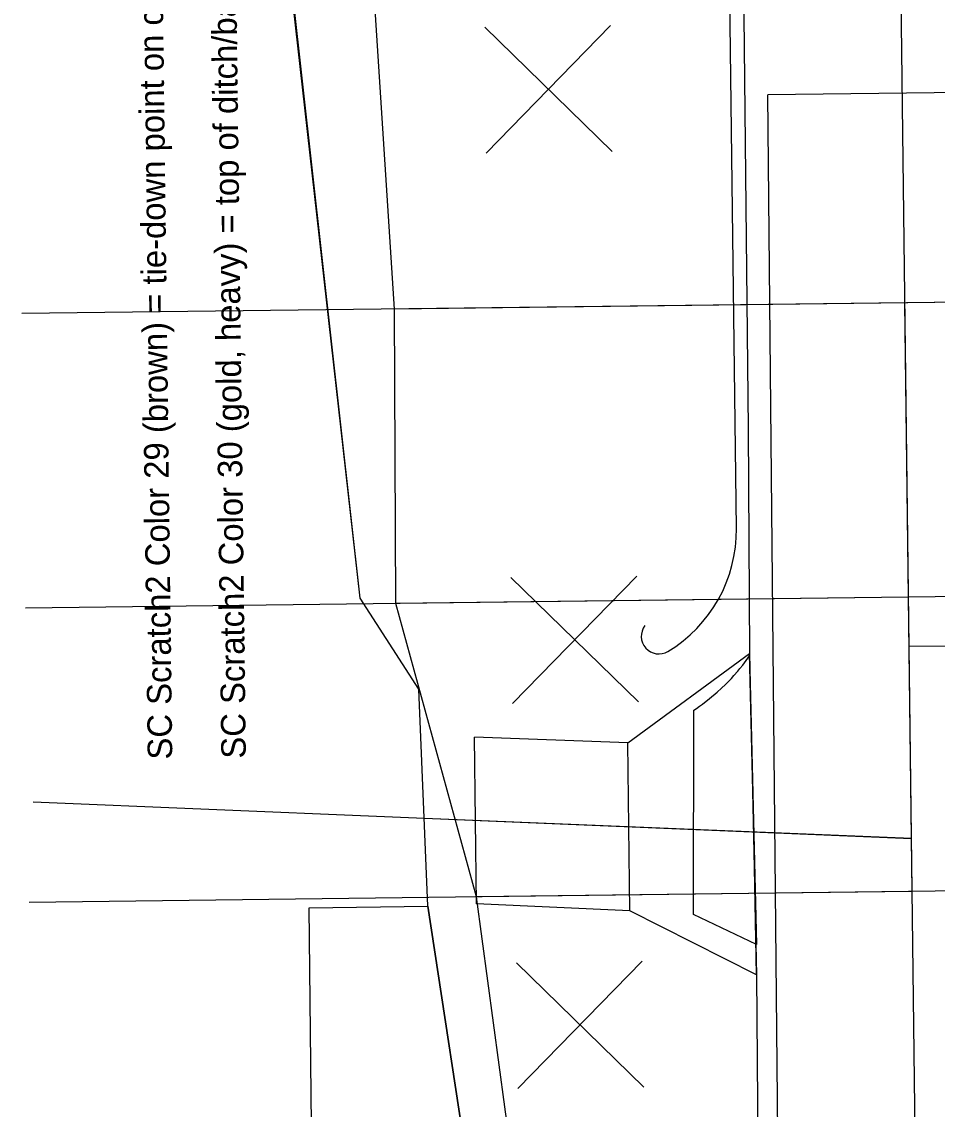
# Model space of a CAD drawing. Extents: x 2341000 to 2341204, y 624110 to 624511.
# Drawn here: x 2341052 to 2341129.8, y 624192 to 624284.3 of the extents above; entities that cross this region are included whole.
import ezdxf

# ---------------------------------------------------------------- set-up
doc = ezdxf.new("R2010")
doc.units = 0
for name, color, linetype in [('Default', 7, 'Continuous'), ('GE_P_Driveway_CL', 7, 'Continuous'), ('PV_P_Drive', 7, 'Continuous'), ('RD_P_GR_Lt', 7, 'Continuous'), ('RD_P_GR_Rt', 7, 'Continuous'), ('RW_P_Const_Limits', 7, 'Continuous'), ('SC_Scratch1', 7, 'Continuous'), ('SC_Scratch10', 7, 'Continuous'), ('SC_Scratch2', 7, 'Continuous'), ('SC_Scratch5', 7, 'Continuous'), ('VG_P_Cells', 7, 'Continuous')]:
    doc.layers.add(name, color=color, linetype=linetype)

msp = doc.modelspace()

# ---------------------------------------------------------------- linework, layer by layer
at = {"layer": 'Default'}
msp.add_line((2341127.658, 624210.478), (2341127.04, 624260.474), dxfattribs=at)
at = {"layer": 'GE_P_Driveway_CL'}
for p, q in [((2341165.46, 624231.741), (2341127.401, 624231.271)), ((2341127.602, 624214.968), (2341087.637, 624216.637))]:
    msp.add_line(p, q, dxfattribs=at)
at = {"layer": 'PV_P_Drive'}
for p, q in [((2341103.5, 624223.114), (2341113.849, 624230.689)), ((2341103.5, 624223.114), (2341090.493, 624223.587)), ((2341090.668, 624209.433), (2341090.493, 624223.587)), ((2341103.676, 624208.846), (2341103.5, 624223.114)), ((2341103.676, 624208.846), (2341090.668, 624209.433)), ((2341114.426, 624203.393), (2341103.676, 624208.846))]:
    msp.add_line(p, q, dxfattribs=at)
msp.add_lwpolyline([(2341114.426, 624203.393), (2341114.204, 624215.528), (2341113.849, 624230.689)], dxfattribs=at)
at = {"layer": 'RD_P_GR_Lt'}
msp.add_line((2341112.726, 624241.296), (2341111.351, 624353.788), dxfattribs=at)
msp.add_arc((2341106.147, 624232.157), 1.5, 143.11049, 300.54947, dxfattribs=at)
at = {"layer": 'RD_P_GR_Rt'}
msp.add_arc((2341100.726, 624241.149), 12, 301.01684, 0.69994, dxfattribs=at)
at = {"layer": 'RW_P_Const_Limits'}
for p, q in [((2341080.795, 624235.399), (2341074.081, 624295.577)), ((2341136.675, 624278.386), (2341115.404, 624278.123)), ((2341116.866, 624125.338), (2341115.404, 624278.123)), ((2341085.756, 624227.657), (2341080.795, 624235.399)), ((2341086.536, 624209.244), (2341085.756, 624227.657))]:
    msp.add_line(p, q, dxfattribs=at)
msp.add_lwpolyline([(2341099.96, 624125.129), (2341096.852, 624159.643), (2341090.335, 624184.21), (2341086.536, 624209.244)], dxfattribs=at)
at = {"layer": 'SC_Scratch1'}
for p, q in [((2341202.034, 624261.401), (2341052.046, 624259.548)), ((2341202.343, 624236.403), (2341052.355, 624234.55)), ((2341053.02, 624218.083), (2341127.602, 624214.968)), ((2341202.652, 624211.405), (2341052.663, 624209.551))]:
    msp.add_line(p, q, dxfattribs=at)
at = {"layer": 'SC_Scratch10'}
msp.add_lwpolyline([(2341113.217, 624298.306), (2341113.72, 624249.79), (2341113.849, 624230.689), (2341114.426, 624203.393), (2341114.82, 624152.66), (2341115.05, 624125.316), (2341099.96, 624125.129), (2341096.852, 624159.643), (2341090.335, 624184.21), (2341086.536, 624209.244), (2341085.756, 624227.657), (2341080.795, 624235.399), (2341072.845, 624305.648)], dxfattribs=at)
msp.add_lwpolyline([(2341099.96, 624125.129), (2341077.357, 624124.82), (2341076.437, 624209.095), (2341086.536, 624209.244), (2341090.335, 624184.21), (2341096.852, 624159.643)], close=True, dxfattribs=at)
at = {"layer": 'SC_Scratch2'}
for p, q in [((2341128.275, 624160.482), (2341124.26, 624485.457)), ((2341155.108, 624260.821), (2341083.683, 624259.939)), ((2341127.349, 624235.476), (2341083.802, 624234.938)), ((2341127.658, 624210.478), (2341090.661, 624210.021))]:
    msp.add_line(p, q, dxfattribs=at)
for points in [[(2341100.878, 624160.143), (2341094.029, 624185.061), (2341090.661, 624210.021), (2341083.802, 624234.938), (2341083.683, 624259.939), (2341082.074, 624284.921), (2341082.174, 624297.923), (2341086.008, 624308.971), (2341075.627, 624317.843), (2341092.175, 624327.049), (2341094.859, 624338.083), (2341094.767, 624360.083), (2341092.498, 624385.057), (2341096.909, 624410.113), (2341097.8, 624435.126)], [(2341083.802, 624234.938), (2341083.683, 624259.939), (2341082.074, 624284.921), (2341082.174, 624297.923)]]:
    msp.add_lwpolyline(points, dxfattribs=at)
at = {"layer": 'SC_Scratch5'}
msp.add_lwpolyline([(2341114.43, 624205.99), (2341109.09, 624208.53), (2341109.12, 624225.88), (2341109.333, 624226.024), (2341109.603, 624226.213), (2341109.849, 624226.392), (2341110.453, 624226.859), (2341111.1, 624227.408), (2341111.465, 624227.742), (2341111.795, 624228.061), (2341112.073, 624228.342), (2341112.298, 624228.58), (2341112.522, 624228.825), (2341112.843, 624229.193), (2341113.029, 624229.415), (2341113.261, 624229.706), (2341113.85, 624230.5)], close=True, dxfattribs=at)
at = {"layer": 'VG_P_Cells'}
for p, q in [((2341091.356, 624283.879), (2341102.179, 624273.32)), ((2341091.489, 624273.188), (2341102.047, 624284.011)), ((2341096.767, 624278.599), (2341096.767, 624278.599)), ((2341093.583, 624237.132), (2341104.406, 624226.573)), ((2341093.715, 624226.441), (2341104.274, 624237.264)), ((2341098.994, 624231.851), (2341098.994, 624231.851)), ((2341094.045, 624204.431), (2341104.868, 624193.872)), ((2341094.177, 624193.74), (2341104.736, 624204.563)), ((2341099.456, 624199.15), (2341099.456, 624199.15))]:
    msp.add_line(p, q, dxfattribs=at)

# ---------------------------------------------------------------- texts
at = {"layer": 'SC_Scratch2'}
for s, p in [('SC Scratch2 Color 29 (brown) = tie-down point on cross sections', (2341064.83, 624221.698)), ('SC Scratch2 Color 30 (gold, heavy) = top of ditch/backslope', (2341071.079, 624221.775))]:
    msp.add_text(s, height=2.08333, rotation=90.70792, dxfattribs=at).set_placement(p)

doc.saveas('drawing.dxf')
